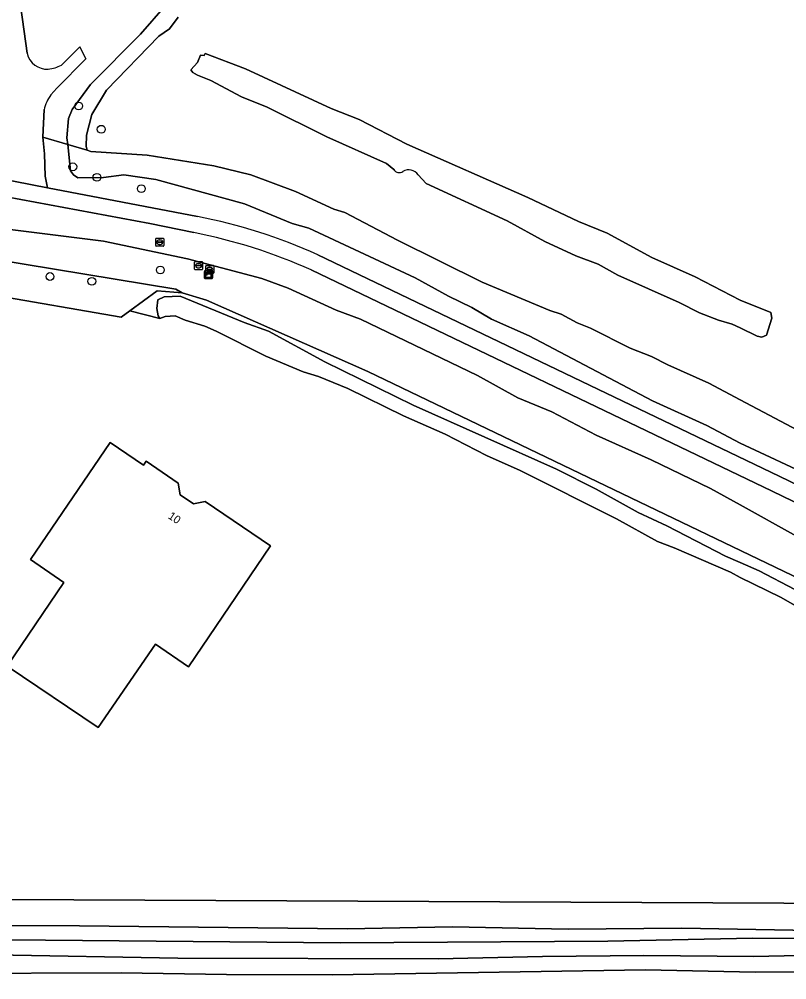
# Model space of a CAD drawing. Extents: x 162156 to 163172, y 378995 to 380779.
# Drawn here: x 162409.9 to 162505.8, y 379596.5 to 379716.5 of the extents above; entities that cross this region are included whole.
import ezdxf

# ---------------------------------------------------------------- set-up
doc = ezdxf.new("R2010")
doc.units = 0
for name, color, linetype in [('IMGEO_Boom', 7, 'Continuous'), ('IMGEO_Brandkraan', 7, 'Continuous'), ('IMGEO_Erf', 7, 'Continuous'), ('IMGEO_Fietspad_gesloten', 7, 'Continuous'), ('IMGEO_Grasland_overig', 7, 'Continuous'), ('IMGEO_Groenvoorziening', 7, 'Continuous'), ('IMGEO_Hek', 7, 'Continuous'), ('IMGEO_Kast', 7, 'Continuous'), ('IMGEO_Loofbos', 7, 'Continuous'), ('IMGEO_Muur', 7, 'Continuous'), ('IMGEO_Pand', 7, 'Continuous'), ('IMGEO_Pand_nummerreeks', 7, 'Continuous'), ('IMGEO_Rijbaan_lokaal_onverhard', 7, 'Continuous'), ('IMGEO_Rioolput', 7, 'Continuous'), ('IMGEO_Waterloop', 7, 'Continuous')]:
    doc.layers.add(name, color=color, linetype=linetype)

msp = doc.modelspace()

# ---------------------------------------------------------------- linework, layer by layer
at = {"layer": 'IMGEO_Boom'}
for centre in [(162417.36, 379705.69), (162420.18, 379702.78), (162416.63, 379698.09), (162419.64, 379696.77), (162425.19, 379695.35), (162427.56, 379685.19), (162413.77, 379684.37), (162419.01, 379683.78)]:
    msp.add_circle(centre, 0.489, dxfattribs=at)
at = {"layer": 'IMGEO_Brandkraan'}
for p, q in [((162426.99, 379688.24), (162426.99, 379689.09)), ((162427.06, 379689.16), (162427.91, 379689.16)), ((162427.99, 379689.09), (162427.99, 379688.24)), ((162427.91, 379688.16), (162427.06, 379688.16)), ((162427.25, 379688.66), (162427.25, 379688.67)), ((162427.29, 379688.71), (162427.69, 379688.71)), ((162427.68, 379688.62), (162427.29, 379688.62)), ((162427.5, 379688.38), (162427.47, 379688.38)), ((162427.48, 379688.94), (162427.5, 379688.94)), ((162427.73, 379688.67), (162427.73, 379688.66))]:
    msp.add_line(p, q, dxfattribs=at)
for points in [[(162426.99, 379688.24), (162426.99, 379689.09)], [(162427.06, 379689.16), (162427.91, 379689.16)], [(162427.99, 379689.09), (162427.99, 379688.24)], [(162427.91, 379688.16), (162427.06, 379688.16)]]:
    msp.add_lwpolyline(points, dxfattribs=at)
for centre, radius, start, end in [((162427.06, 379689.09), 0.0765, 91.552, 178.448), ((162427.06, 379689.09), 0.0765, 91.552, 178.448), ((162427.91, 379689.09), 0.0765, 1.552, 88.448), ((162427.91, 379689.09), 0.0765, 1.552, 88.448), ((162427.06, 379688.24), 0.0765, 181.552, 268.448), ((162427.06, 379688.24), 0.0765, 181.552, 268.448), ((162427.29, 379688.67), 0.0403, 85.8775, 175.7526), ((162427.28, 379688.66), 0.0366, 178.938, 274.7102), ((162427.69, 379688.66), 0.043, 264.8664, 352.4533), ((162427.69, 379688.67), 0.0386, 1.7309, 96.639), ((162427.91, 379688.24), 0.0765, 271.552, 358.448), ((162427.91, 379688.24), 0.0765, 271.552, 358.448)]:
    msp.add_arc(centre, radius, start, end, dxfattribs=at)
for centre, major_axis, ratio, start_param, end_param in [((162427.47, 379688.66), (-0.387, 0.002), 0.722429, 4.712389, 7.853982), ((162427.5, 379688.66), (-0.39, 0.002), 0.717154, 1.570796, 4.712389)]:
    msp.add_ellipse(centre, major_axis=major_axis, ratio=ratio, start_param=start_param, end_param=end_param, dxfattribs=at)
at = {"layer": 'IMGEO_Erf'}
for points in [[(162484.57, 379654.08), (162472.51, 379660.13), (162468.34, 379662), (162463.16, 379664.66), (162457.94, 379666.98), (162451, 379670.36), (162447.34, 379671.86), (162445.4, 379672.46), (162440.74, 379674.41), (162434.55, 379677.53), (162433.12, 379678.16), (162430.65, 379678.9), (162429.43, 379679.48), (162428.15, 379679.38), (162427.51, 379679.12), (162423.76, 379680.09), (162422.68, 379679.3), (162406.24, 379682.12)], [(162381.21, 379606.63), (162576.44, 379605.74), (162576.49, 379606.38), (162549.78, 379622.05), (162534.44, 379629.57), (162530.51, 379631.35), (162528.99, 379632.22), (162528.47, 379632.7), (162526.23, 379634.14), (162524.52, 379635.06), (162522, 379636.11), (162518.78, 379637.9), (162515.33, 379639.11), (162512.47, 379640.47), (162510.75, 379641.07), (162505.07, 379644.31), (162500, 379646.77), (162498.81, 379647.43), (162491.76, 379650.47), (162489.68, 379651.24), (162484.57, 379654.08)]]:
    msp.add_lwpolyline(points, dxfattribs=at)
msp.add_lwpolyline([(162415.52, 379646.14), (162411.33, 379649.02), (162421.29, 379663.64), (162425.48, 379660.81), (162425.79, 379661.28), (162429.79, 379658.54), (162430.06, 379657.09), (162431.71, 379655.98), (162433.15, 379656.25), (162441.34, 379650.7), (162431.1, 379635.6), (162426.95, 379638.44), (162419.81, 379628), (162408.42, 379635.69)], close=True, dxfattribs=at)
at = {"layer": 'IMGEO_Fietspad_gesloten'}
for points in [[(162413.48, 379695.46), (162407.27, 379696.65), (162406.55, 379696.77), (162403.9, 379697.22), (162359.69, 379704.68), (162325.62, 379710.33), (162314.3, 379712.21), (162298.24, 379714.87), (162294.27, 379715.59)], [(162293.88, 379713.56), (162297.83, 379712.83), (162406.51, 379694.67), (162426.26, 379691.02), (162431.74, 379689.86)], [(162432.21, 379691.87), (162413.48, 379695.46)], [(162562.54, 379631.4), (162559.89, 379632.75), (162557.48, 379633.98), (162556.84, 379634.31), (162504.9, 379659.41), (162447.23, 379687.09)], [(162446.41, 379685.19), (162504, 379657.56), (162555.93, 379632.44), (162561.58, 379629.6)]]:
    msp.add_lwpolyline(points, dxfattribs=at)
for centre, radius, start, end in [((162419.44, 379625.71), 67.38, 65.6396, 79.0765), ((162418.79, 379623.79), 67.33, 65.7839, 78.9097)]:
    msp.add_arc(centre, radius, start, end, dxfattribs=at)
at = {"layer": 'IMGEO_Grasland_overig'}
for points in [[(162431.74, 379689.86), (162426.26, 379691.02), (162406.51, 379694.67), (162297.83, 379712.83)], [(162406.42, 379690.54), (162420.47, 379688.81), (162430.94, 379686.6), (162440.24, 379684.12), (162443.52, 379682.91), (162449.55, 379680.16), (162452.58, 379679.03), (162467.18, 379672.02), (162472.24, 379669.23), (162476.49, 379667.45), (162482.03, 379664.56), (162488.91, 379661.45), (162496.32, 379657.89), (162500, 379655.84), (162507.07, 379651.91), (162527, 379642.11), (162536.23, 379637.93), (162571.68, 379620.55), (162577.82, 379616.97), (162589.02, 379609.76), (162590.32, 379608.63), (162594.66, 379608.63), (162575.95, 379621.11)], [(162561.58, 379629.6), (162555.93, 379632.44), (162504, 379657.56), (162446.41, 379685.19)]]:
    msp.add_lwpolyline(points, dxfattribs=at)
msp.add_arc((162418.79, 379623.79), 67.33, 65.7839, 78.9097, dxfattribs=at)
at = {"layer": 'IMGEO_Groenvoorziening'}
for points in [[(162509.49, 379659.13), (162500, 379663.53), (162495.85, 379665.74), (162489.06, 379668.85), (162473.64, 379676.97), (162468.93, 379679.03), (162466.49, 379680.49), (162463.56, 379681.92), (162459.42, 379684.2), (162446.1, 379690.4), (162444.05, 379691.02), (162438.08, 379693.47), (162427.01, 379696.5), (162423.01, 379697.07), (162420.45, 379696.73), (162417.25, 379696.72), (162416.72, 379697.08), (162416.35, 379697.6), (162415.99, 379700.88), (162412.89, 379701.78), (162413.08, 379699.72), (162413.18, 379696.91), (162413.48, 379695.46), (162432.21, 379691.87)], [(162447.23, 379687.09), (162504.9, 379659.41), (162556.84, 379634.31)], [(162537.26, 379632.25), (162453.48, 379672.51), (162433.35, 379681.42), (162430.28, 379682.33), (162427.17, 379682.58), (162423.76, 379680.09), (162427.51, 379679.12), (162427.28, 379679.47), (162427.13, 379680.38), (162427.24, 379681.45), (162428.04, 379681.84), (162430.05, 379681.9), (162438.03, 379678.63), (162441.1, 379677.53), (162448.12, 379673.72), (162459.17, 379668.3), (162477.08, 379660.29), (162482.01, 379657.8), (162487.26, 379654.89), (162490.86, 379653.23), (162498.17, 379649.41), (162500, 379648.62), (162502.39, 379647.6), (162506.86, 379645.24)], [(162402.03, 379603.27), (162417.45, 379603.23), (162450.9, 379602.84), (162464.08, 379603.1), (162478.54, 379602.81), (162492.71, 379602.92), (162508.94, 379602.64), (162525.01, 379602.55), (162557.68, 379602.05), (162573.91, 379602.07), (162583.87, 379601.63), (162579, 379604.91), (162576.49, 379606.38), (162576.44, 379605.74), (162381.21, 379606.63)], [(162599.36, 379600.44), (162589.22, 379601.32), (162587.44, 379601.47), (162583.87, 379601.63), (162573.91, 379602.07), (162557.68, 379602.05), (162525.01, 379602.55), (162508.94, 379602.64), (162492.71, 379602.92), (162478.54, 379602.81), (162464.08, 379603.1), (162450.9, 379602.84), (162417.45, 379603.23), (162402.03, 379603.27)], [(162390.14, 379601.66), (162450.09, 379601.12), (162483.49, 379601.33), (162501.57, 379601.68), (162517.5, 379601.59), (162533.57, 379601.39), (162564.43, 379600.52), (162577.81, 379600.87), (162587.65, 379600.27), (162599.79, 379599)], [(162597.2, 379597.21), (162590.45, 379597.45), (162582.36, 379597.47), (162571.83, 379598.01), (162559.51, 379598.29), (162513.07, 379599.65), (162501.71, 379599.4), (162488, 379599.51), (162475.33, 379599.41), (162462.3, 379599.1), (162429.76, 379599.2), (162406.83, 379599.61)], [(162400.18, 379597.26), (162422.68, 379597.35), (162435.85, 379597.13), (162449.03, 379597.12), (162488.2, 379597.72), (162501.89, 379597.42), (162513.24, 379597.48), (162525.7, 379597.25), (162539.65, 379596.72), (162554.31, 379596.32)], [(162554.31, 379596.32), (162539.65, 379596.72), (162525.7, 379597.25), (162513.24, 379597.48), (162501.89, 379597.42), (162488.2, 379597.72), (162449.03, 379597.12), (162435.85, 379597.13), (162422.68, 379597.35), (162400.18, 379597.26)]]:
    msp.add_lwpolyline(points, dxfattribs=at)
msp.add_lwpolyline([(162430.28, 379682.33), (162429.51, 379682.78), (162345.56, 379696.61), (162344.76, 379695.24), (162343.93, 379693.83), (162342.98, 379692.21), (162342.56, 379688.42), (162343.87, 379688.35), (162347.07, 379692.29), (162406.24, 379682.12), (162422.68, 379679.3), (162423.76, 379680.09), (162427.17, 379682.58)], close=True, dxfattribs=at)
msp.add_arc((162419.44, 379625.71), 67.38, 65.6396, 79.0765, dxfattribs=at)
at = {"layer": 'IMGEO_Hek'}
for points in [[(162406.24, 379682.12), (162422.68, 379679.3), (162423.76, 379680.09)], [(162423.76, 379680.09), (162427.17, 379682.58), (162430.28, 379682.33)], [(162430.28, 379682.33), (162433.35, 379681.42), (162453.48, 379672.51), (162537.26, 379632.25), (162548.18, 379626.94), (162556.22, 379622.82), (162565.4, 379617.82), (162571.38, 379614.13), (162576.79, 379610.34)]]:
    msp.add_lwpolyline(points, dxfattribs=at)
at = {"layer": 'IMGEO_Kast'}
for p, q in [((162433.08, 379684.18), (162433.08, 379685.02)), ((162433.08, 379685.02), (162433.08, 379684.18)), ((162433.15, 379685.11), (162433.99, 379685.11)), ((162433.99, 379685.11), (162433.15, 379685.11)), ((162434.08, 379685.03), (162434.08, 379684.19)), ((162434.08, 379684.19), (162434.08, 379685.03)), ((162434, 379684.11), (162433.16, 379684.11)), ((162433.16, 379684.11), (162434, 379684.11))]:
    msp.add_line(p, q, dxfattribs=at)
for points in [[(162433.27, 379684.9), (162433.87, 379684.9), (162433.87, 379684.81), (162433.27, 379684.81), (162433.27, 379684.9)], [(162433.27, 379684.72), (162433.87, 379684.72), (162433.87, 379684.24), (162433.27, 379684.24), (162433.27, 379684.72)]]:
    msp.add_lwpolyline(points, dxfattribs=at)
msp.add_circle((162433.36, 379684.57), 0.0377, dxfattribs=at)
for centre, start, end in [((162433.16, 379685.03), 92.4484, 184.2845), ((162433.16, 379685.03), 92.4484, 184.2845), ((162434, 379685.03), 2.4484, 94.2845), ((162434, 379685.03), 2.4484, 94.2845), ((162433.16, 379684.19), 182.4484, 274.2845), ((162433.16, 379684.19), 182.4484, 274.2845), ((162434, 379684.19), 272.4484, 4.2845), ((162434, 379684.19), 272.4484, 4.2845)]:
    msp.add_arc(centre, 0.0779, start, end, dxfattribs=at)
at = {"layer": 'IMGEO_Loofbos'}
for points in [[(162407.9, 379787.07), (162404.33, 379784.27), (162403, 379782.61), (162402.58, 379781.28), (162405.36, 379754.23), (162407.92, 379733.94), (162410.93, 379712.28)], [(162413.05, 379705.23), (162412.89, 379701.78), (162415.99, 379700.88), (162415.89, 379701.72), (162416.07, 379704.11), (162416.53, 379705.25), (162418.82, 379708.37), (162425.07, 379714.68), (162428.19, 379718.23), (162429.87, 379719.79), (162431.45, 379721.79), (162433.88, 379726.03), (162434.41, 379727.38), (162434.93, 379729.62), (162434.96, 379731.45), (162434.82, 379732.58), (162434.21, 379734.79), (162431.84, 379739.92), (162430.72, 379741.38), (162429.29, 379744.28), (162428.39, 379748.48), (162428.43, 379750), (162428.47, 379751.52)], [(162429.81, 379716.79), (162428.73, 379715.33), (162427.37, 379714.41), (162420.85, 379707.67), (162419.01, 379704.63), (162418.33, 379702.03), (162418.29, 379700.63), (162418.41, 379700.17), (162418.87, 379700), (162425.92, 379699.54), (162434.27, 379698.21), (162438.86, 379697.09), (162444.46, 379695), (162449.24, 379692.79), (162450.6, 379692.37), (162457.18, 379688.91), (162467.77, 379683.67), (162476.24, 379680.12), (162477.66, 379679.66), (162479.66, 379678.58), (162481.32, 379677.92), (162486.27, 379675.43), (162488.93, 379674.39), (162490.98, 379673.33), (162496.1, 379671.04), (162500, 379668.98), (162508.68, 379664.39)], [(162415.21, 379710.79), (162417.5, 379713.07), (162418.27, 379711.58), (162414.63, 379707.93), (162413.9, 379707.07)], [(162456.73, 379697.73), (162455.84, 379698.5), (162448.35, 379701.85), (162440.91, 379705.54), (162437.69, 379706.82), (162433.86, 379708.86), (162432.22, 379709.52), (162431.61, 379709.88), (162431.36, 379710.19), (162432.21, 379711.14), (162432.6, 379712.03), (162433.03, 379711.98), (162433.16, 379712.25), (162438.21, 379710.32), (162448.92, 379705.39), (162452.41, 379704.01), (162458.35, 379700.92), (162473.48, 379694.26), (162479.83, 379691.23), (162483.39, 379689.79), (162488.98, 379686.75), (162494.39, 379684.33), (162500, 379681.41), (162503.86, 379679.87), (162503.98, 379679.17), (162503.32, 379677.05), (162502.74, 379676.79), (162502.14, 379676.94), (162500, 379677.97), (162499.02, 379678.44), (162497.3, 379678.9), (162494.95, 379679.84), (162492.41, 379681.12), (162484.72, 379684.55), (162482.26, 379685.91), (162479.47, 379686.98), (162475.6, 379688.76), (162470.9, 379691.35), (162460.78, 379696.01), (162459.77, 379697.07)], [(162345.56, 379696.61), (162429.51, 379682.78), (162430.28, 379682.33), (162433.35, 379681.42), (162453.48, 379672.51), (162537.26, 379632.25)], [(162507.07, 379651.91), (162500, 379655.84), (162496.32, 379657.89), (162488.91, 379661.45), (162482.03, 379664.56), (162476.49, 379667.45), (162472.24, 379669.23), (162467.18, 379672.02), (162452.58, 379679.03), (162449.55, 379680.16), (162443.52, 379682.91), (162440.24, 379684.12), (162430.94, 379686.6), (162420.47, 379688.81), (162406.42, 379690.54)]]:
    msp.add_lwpolyline(points, dxfattribs=at)
for centre, radius, start, end in [((162413.41, 379712.84), 2.55, 192.822, 273.2988), ((162413.15, 379714.75), 4.46, 275.2213, 297.5353), ((162417.24, 379704.4), 4.27, 141.4627, 168.8525), ((162457.42, 379698.18), 0.82, 213.2112, 304.3225), ((162458.61, 379696.34), 1.38, 32.0229, 121.8774)]:
    msp.add_arc(centre, radius, start, end, dxfattribs=at)
at = {"layer": 'IMGEO_Muur'}
msp.add_lwpolyline([(162381.21, 379606.63), (162576.44, 379605.74), (162576.49, 379606.38)], dxfattribs=at)
at = {"layer": 'IMGEO_Pand'}
msp.add_lwpolyline([(162408.42, 379635.69), (162419.81, 379628), (162426.95, 379638.44), (162431.1, 379635.6), (162441.34, 379650.7), (162433.15, 379656.25), (162431.71, 379655.98), (162430.06, 379657.09), (162429.79, 379658.54), (162425.79, 379661.28), (162425.48, 379660.81), (162421.29, 379663.64), (162411.33, 379649.02), (162415.52, 379646.14)], close=True, dxfattribs=at)
at = {"layer": 'IMGEO_Rijbaan_lokaal_onverhard'}
for points in [[(162410.93, 379712.28), (162407.92, 379733.94), (162405.36, 379754.23), (162402.58, 379781.28), (162403, 379782.61), (162404.33, 379784.27), (162407.9, 379787.07)], [(162413.9, 379707.07), (162414.63, 379707.93), (162418.27, 379711.58), (162417.5, 379713.07), (162415.21, 379710.79)], [(162407.27, 379696.65), (162413.48, 379695.46), (162413.18, 379696.91), (162413.08, 379699.72), (162412.89, 379701.78), (162413.05, 379705.23)]]:
    msp.add_lwpolyline(points, dxfattribs=at)
for centre, radius, start, end in [((162413.41, 379712.84), 2.55, 192.822, 273.2988), ((162413.15, 379714.75), 4.46, 275.2213, 297.5353), ((162417.24, 379704.4), 4.27, 141.4627, 168.8525)]:
    msp.add_arc(centre, radius, start, end, dxfattribs=at)
at = {"layer": 'IMGEO_Rioolput'}
for p, q in [((162431.84, 379685.31), (162431.84, 379686.16)), ((162431.92, 379686.24), (162432.77, 379686.24)), ((162432.1, 379685.73), (162432.1, 379685.74)), ((162432.54, 379685.69), (162432.14, 379685.69)), ((162432.15, 379685.78), (162432.54, 379685.78)), ((162432.33, 379686.01), (162432.36, 379686.01)), ((162432.59, 379685.74), (162432.59, 379685.73)), ((162432.85, 379686.16), (162432.85, 379685.31)), ((162433.23, 379684.83), (162433.23, 379685.68)), ((162433.31, 379685.75), (162434.16, 379685.75)), ((162433.72, 379685.53), (162433.75, 379685.53)), ((162434.23, 379685.68), (162434.23, 379684.83)), ((162432.77, 379685.23), (162431.92, 379685.23)), ((162432.35, 379685.46), (162432.33, 379685.46)), ((162434.16, 379684.75), (162433.31, 379684.75)), ((162433.49, 379685.25), (162433.49, 379685.26)), ((162433.93, 379685.21), (162433.53, 379685.21)), ((162433.54, 379685.3), (162433.93, 379685.3)), ((162433.74, 379684.97), (162433.72, 379684.97)), ((162433.98, 379685.26), (162433.98, 379685.25))]:
    msp.add_line(p, q, dxfattribs=at)
for points in [[(162431.84, 379685.31), (162431.84, 379686.16)], [(162431.92, 379686.24), (162432.77, 379686.24)], [(162432.85, 379686.16), (162432.85, 379685.31)], [(162433.23, 379684.83), (162433.23, 379685.68)], [(162433.31, 379685.75), (162434.16, 379685.75)], [(162434.23, 379685.68), (162434.23, 379684.83)], [(162432.77, 379685.23), (162431.92, 379685.23)], [(162434.16, 379684.75), (162433.31, 379684.75)]]:
    msp.add_lwpolyline(points, dxfattribs=at)
for centre, radius, start, end in [((162431.92, 379686.16), 0.0765, 91.552, 178.448), ((162431.92, 379686.16), 0.0765, 91.552, 178.448), ((162432.14, 379685.74), 0.0403, 85.8775, 175.7526), ((162432.14, 379685.73), 0.0366, 178.938, 274.7102), ((162432.55, 379685.74), 0.0386, 1.7309, 96.639), ((162432.54, 379685.73), 0.043, 264.8664, 352.4533), ((162432.77, 379686.16), 0.0765, 1.552, 88.448), ((162432.77, 379686.16), 0.0765, 1.552, 88.448), ((162433.31, 379685.68), 0.0765, 91.552, 178.448), ((162433.31, 379685.68), 0.0765, 91.552, 178.448), ((162434.16, 379685.68), 0.0765, 1.552, 88.448), ((162434.16, 379685.68), 0.0765, 1.552, 88.448), ((162431.92, 379685.31), 0.0765, 181.552, 268.448), ((162431.92, 379685.31), 0.0765, 181.552, 268.448), ((162432.77, 379685.31), 0.0765, 271.552, 358.448), ((162432.77, 379685.31), 0.0765, 271.552, 358.448), ((162433.31, 379684.83), 0.0765, 181.552, 268.448), ((162433.31, 379684.83), 0.0765, 181.552, 268.448), ((162433.53, 379685.26), 0.0403, 85.8775, 175.7526), ((162433.53, 379685.25), 0.0366, 178.938, 274.7102), ((162433.94, 379685.26), 0.0386, 1.7309, 96.639), ((162433.93, 379685.25), 0.043, 264.8664, 352.4533), ((162434.16, 379684.83), 0.0765, 271.552, 358.448), ((162434.16, 379684.83), 0.0765, 271.552, 358.448)]:
    msp.add_arc(centre, radius, start, end, dxfattribs=at)
for centre, major_axis, ratio, start_param, end_param in [((162432.33, 379685.73), (-0.387, 0.002), 0.722429, 4.712389, 7.853982), ((162432.36, 379685.73), (-0.39, 0.002), 0.717154, 1.570796, 4.712389), ((162433.72, 379685.25), (-0.387, 0.002), 0.722429, 4.712389, 7.853982), ((162433.74, 379685.25), (-0.39, 0.002), 0.717154, 1.570796, 4.712389)]:
    msp.add_ellipse(centre, major_axis=major_axis, ratio=ratio, start_param=start_param, end_param=end_param, dxfattribs=at)
at = {"layer": 'IMGEO_Waterloop'}
for points in [[(162428.19, 379718.23), (162425.07, 379714.68), (162418.82, 379708.37), (162416.53, 379705.25), (162416.07, 379704.11), (162415.89, 379701.72), (162415.99, 379700.88), (162418.41, 379700.17), (162418.29, 379700.63), (162418.33, 379702.03), (162419.01, 379704.63), (162420.85, 379707.67), (162427.37, 379714.41), (162428.73, 379715.33), (162429.81, 379716.79)], [(162459.77, 379697.07), (162460.78, 379696.01), (162470.9, 379691.35), (162475.6, 379688.76), (162479.47, 379686.98), (162482.26, 379685.91), (162484.72, 379684.55), (162492.41, 379681.12), (162494.95, 379679.84), (162497.3, 379678.9), (162499.02, 379678.44), (162500, 379677.97), (162502.14, 379676.94), (162502.74, 379676.79), (162503.32, 379677.05), (162503.98, 379679.17), (162503.86, 379679.87), (162500, 379681.41), (162494.39, 379684.33), (162488.98, 379686.75), (162483.39, 379689.79), (162479.83, 379691.23), (162473.48, 379694.26), (162458.35, 379700.92), (162452.41, 379704.01), (162448.92, 379705.39), (162438.21, 379710.32), (162433.16, 379712.25), (162433.03, 379711.98), (162432.6, 379712.03), (162432.21, 379711.14), (162431.36, 379710.19), (162431.61, 379709.88), (162432.22, 379709.52), (162433.86, 379708.86), (162437.69, 379706.82), (162440.91, 379705.54), (162448.35, 379701.85), (162455.84, 379698.5), (162456.73, 379697.73)], [(162508.68, 379664.39), (162500, 379668.98), (162496.1, 379671.04), (162490.98, 379673.33), (162488.93, 379674.39), (162486.27, 379675.43), (162481.32, 379677.92), (162479.66, 379678.58), (162477.66, 379679.66), (162476.24, 379680.12), (162467.77, 379683.67), (162457.18, 379688.91), (162450.6, 379692.37), (162449.24, 379692.79), (162444.46, 379695), (162438.86, 379697.09), (162434.27, 379698.21), (162425.92, 379699.54), (162418.87, 379700), (162418.41, 379700.17), (162415.99, 379700.88), (162416.35, 379697.6), (162416.72, 379697.08), (162417.25, 379696.72), (162420.45, 379696.73), (162423.01, 379697.07), (162427.01, 379696.5), (162438.08, 379693.47), (162444.05, 379691.02), (162446.1, 379690.4), (162459.42, 379684.2), (162463.56, 379681.92), (162466.49, 379680.49), (162468.93, 379679.03), (162473.64, 379676.97), (162489.06, 379668.85), (162495.85, 379665.74), (162500, 379663.53), (162509.49, 379659.13)], [(162506.86, 379645.24), (162502.39, 379647.6), (162500, 379648.62), (162498.17, 379649.41), (162490.86, 379653.23), (162487.26, 379654.89), (162482.01, 379657.8), (162477.08, 379660.29), (162459.17, 379668.3), (162448.12, 379673.72), (162441.1, 379677.53), (162438.03, 379678.63), (162430.05, 379681.9), (162428.04, 379681.84), (162427.24, 379681.45), (162427.13, 379680.38), (162427.28, 379679.47), (162427.51, 379679.12), (162428.15, 379679.38), (162429.43, 379679.48), (162430.65, 379678.9), (162433.12, 379678.16), (162434.55, 379677.53), (162440.74, 379674.41), (162445.4, 379672.46), (162447.34, 379671.86), (162451, 379670.36), (162457.94, 379666.98), (162463.16, 379664.66), (162468.34, 379662), (162472.51, 379660.13), (162484.57, 379654.08), (162489.68, 379651.24), (162491.76, 379650.47), (162498.81, 379647.43), (162500, 379646.77), (162505.07, 379644.31), (162510.75, 379641.07)], [(162599.79, 379599), (162587.65, 379600.27), (162577.81, 379600.87), (162564.43, 379600.52), (162533.57, 379601.39), (162517.5, 379601.59), (162501.57, 379601.68), (162483.49, 379601.33), (162450.09, 379601.12), (162390.14, 379601.66)], [(162406.83, 379599.61), (162429.76, 379599.2), (162462.3, 379599.1), (162475.33, 379599.41), (162488, 379599.51), (162501.71, 379599.4), (162513.07, 379599.65), (162559.51, 379598.29), (162571.83, 379598.01), (162582.36, 379597.47), (162590.45, 379597.45), (162597.2, 379597.21)]]:
    msp.add_lwpolyline(points, dxfattribs=at)
for centre, radius, start, end in [((162457.42, 379698.18), 0.82, 213.2112, 304.3225), ((162458.61, 379696.34), 1.38, 32.0229, 121.8774)]:
    msp.add_arc(centre, radius, start, end, dxfattribs=at)

# ---------------------------------------------------------------- texts
at = {"layer": 'IMGEO_Pand_nummerreeks'}
msp.add_text('10', height=1, rotation=326.078, dxfattribs=at).set_placement((162428.45, 379654.22))

doc.saveas('drawing.dxf')
